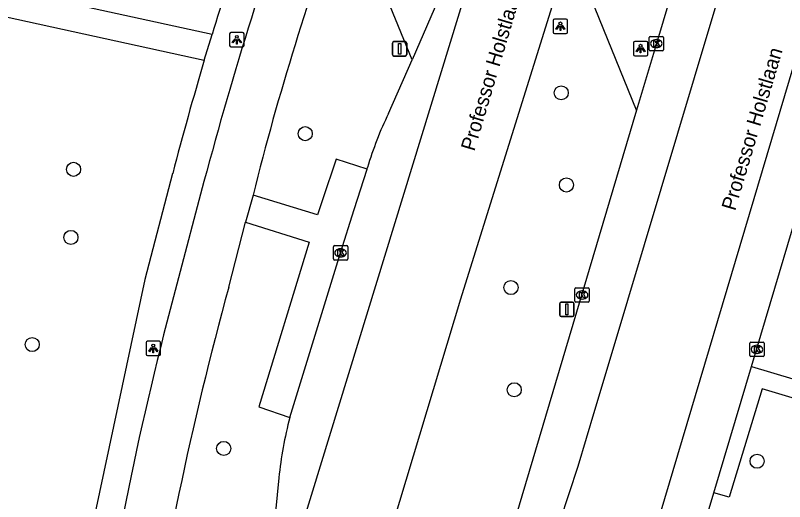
# Model space of a CAD drawing. Extents: x 159822 to 160765, y 380693 to 381634.
# Drawn here: x 160379.6 to 160432.9, y 380824 to 380857.8 of the extents above; entities that cross this region are included whole.
import ezdxf

# ---------------------------------------------------------------- set-up
doc = ezdxf.new("R2010")
doc.units = 0
for name, color, linetype in [('IMGEO_Berm_groen', 7, 'Continuous'), ('IMGEO_Boom', 7, 'Continuous'), ('IMGEO_Fietspad_gesloten', 7, 'Continuous'), ('IMGEO_Kolk', 7, 'Continuous'), ('IMGEO_Lichtpunt', 7, 'Continuous'), ('IMGEO_Openbare_ruimte_label', 7, 'Continuous'), ('IMGEO_Rijbaan_regionaal_gesloten', 7, 'Continuous'), ('IMGEO_Verkeersbordpaal', 7, 'Continuous'), ('IMGEO_Voetpad_halfverhard', 7, 'Continuous'), ('IMGEO_Voetpad_open', 7, 'Continuous')]:
    doc.layers.add(name, color=color, linetype=linetype)

msp = doc.modelspace()

# ---------------------------------------------------------------- linework, layer by layer
at = {"layer": 'IMGEO_Berm_groen'}
for points in [[(160407.126, 380854.699), (160402.508, 380865.998)], [(160422.694, 380851.192), (160418.106, 380862.477)]]:
    msp.add_lwpolyline(points, dxfattribs=at)
at = {"layer": 'IMGEO_Boom'}
for centre in [(160417.464, 380852.4), (160399.725, 380849.567), (160383.666, 380847.093), (160417.825, 380846.009), (160383.487, 380842.374), (160413.984, 380838.893), (160380.802, 380834.941), (160414.212, 380831.806), (160394.076, 380827.737), (160431.038, 380826.852)]:
    msp.add_circle(centre, 0.489, dxfattribs=at)
at = {"layer": 'IMGEO_Fietspad_gesloten'}
for points in [[(160392.709, 380846.25), (160390.838, 380839.14)], [(160396.107, 380845.302), (160395.593, 380843.438)], [(160394.421, 380838.922), (160395.593, 380843.438)]]:
    msp.add_lwpolyline(points, dxfattribs=at)
for centre, radius, start, end in [((160654.597, 380776.451), 271.03, 160.08749, 165.07638), ((160585.377, 380798.101), 195.067, 159.63071, 165.997), ((160619.543, 380777.36), 236.902, 164.8836, 171.94842), ((160622.56, 380776.424), 236.545, 164.67983, 171.81298)]:
    msp.add_arc(centre, radius, start, end, dxfattribs=at)
at = {"layer": 'IMGEO_Kolk'}
for p, q in [((160423.557, 380855.39), (160423.557, 380856.242)), ((160423.632, 380856.316), (160424.484, 380856.316)), ((160424.045, 380856.096), (160424.07, 380856.096)), ((160424.558, 380856.242), (160424.558, 380855.39)), ((160424.068, 380855.536), (160424.043, 380855.536)), ((160424.484, 380855.316), (160423.632, 380855.316)), ((160401.674, 380840.876), (160401.674, 380841.728)), ((160401.749, 380841.802), (160402.601, 380841.802)), ((160402.162, 380841.582), (160402.187, 380841.582)), ((160402.675, 380841.728), (160402.675, 380840.876)), ((160402.185, 380841.022), (160402.16, 380841.022)), ((160402.601, 380840.802), (160401.749, 380840.802)), ((160418.41, 380837.952), (160418.41, 380838.804)), ((160418.485, 380838.878), (160419.337, 380838.878)), ((160418.898, 380838.658), (160418.923, 380838.658)), ((160419.411, 380838.804), (160419.411, 380837.952)), ((160419.337, 380837.878), (160418.485, 380837.878)), ((160418.921, 380838.098), (160418.896, 380838.098)), ((160430.532, 380834.182), (160430.532, 380835.034)), ((160430.607, 380835.108), (160431.459, 380835.108)), ((160431.02, 380834.888), (160431.045, 380834.888)), ((160431.533, 380835.034), (160431.533, 380834.182)), ((160431.459, 380834.108), (160430.607, 380834.108)), ((160431.043, 380834.328), (160431.018, 380834.328))]:
    msp.add_line(p, q, dxfattribs=at)
for points in [[(160423.557, 380855.39), (160423.557, 380856.242)], [(160423.632, 380856.316), (160424.484, 380856.316)], [(160423.878, 380856.016), (160424.001, 380856.016), (160424.001, 380855.865), (160424.131, 380856.016), (160424.295, 380856.016), (160424.149, 380855.865), (160424.302, 380855.616), (160424.15, 380855.616), (160424.065, 380855.78), (160424.001, 380855.713), (160424.001, 380855.616), (160423.878, 380855.616), (160423.878, 380856.016)], [(160424.558, 380856.242), (160424.558, 380855.39)], [(160424.484, 380855.316), (160423.632, 380855.316)], [(160401.674, 380840.876), (160401.674, 380841.728)], [(160401.749, 380841.802), (160402.601, 380841.802)], [(160402.675, 380841.728), (160402.675, 380840.876)], [(160401.995, 380841.502), (160402.118, 380841.502), (160402.118, 380841.351), (160402.248, 380841.502), (160402.412, 380841.502), (160402.266, 380841.351), (160402.419, 380841.102), (160402.267, 380841.102), (160402.182, 380841.266), (160402.118, 380841.199), (160402.118, 380841.102), (160401.995, 380841.102), (160401.995, 380841.502)], [(160402.601, 380840.802), (160401.749, 380840.802)], [(160418.41, 380837.952), (160418.41, 380838.804)], [(160418.485, 380838.878), (160419.337, 380838.878)], [(160418.731, 380838.578), (160418.854, 380838.578), (160418.854, 380838.427), (160418.984, 380838.578), (160419.148, 380838.578), (160419.002, 380838.427), (160419.155, 380838.178), (160419.003, 380838.178), (160418.918, 380838.342), (160418.854, 380838.275), (160418.854, 380838.178), (160418.731, 380838.178), (160418.731, 380838.578)], [(160419.411, 380838.804), (160419.411, 380837.952)], [(160419.337, 380837.878), (160418.485, 380837.878)], [(160430.532, 380834.182), (160430.532, 380835.034)], [(160430.607, 380835.108), (160431.459, 380835.108)], [(160430.853, 380834.808), (160430.976, 380834.808), (160430.976, 380834.657), (160431.106, 380834.808), (160431.27, 380834.808), (160431.124, 380834.657), (160431.277, 380834.408), (160431.125, 380834.408), (160431.04, 380834.572), (160430.976, 380834.505), (160430.976, 380834.408), (160430.853, 380834.408), (160430.853, 380834.808)], [(160431.533, 380835.034), (160431.533, 380834.182)], [(160431.459, 380834.108), (160430.607, 380834.108)]]:
    msp.add_lwpolyline(points, dxfattribs=at)
for centre, start, end in [((160423.634, 380856.24), 91.552, 178.448), ((160423.634, 380856.24), 91.552, 178.448), ((160424.482, 380856.24), 1.552, 88.448), ((160424.482, 380856.24), 1.552, 88.448), ((160423.634, 380855.392), 181.552, 268.448), ((160423.634, 380855.392), 181.552, 268.448), ((160424.482, 380855.392), 271.552, 358.448), ((160424.482, 380855.392), 271.552, 358.448), ((160401.751, 380841.726), 91.552, 178.448), ((160401.751, 380841.726), 91.552, 178.448), ((160402.599, 380841.726), 1.552, 88.448), ((160402.599, 380841.726), 1.552, 88.448), ((160401.751, 380840.878), 181.552, 268.448), ((160401.751, 380840.878), 181.552, 268.448), ((160402.599, 380840.878), 271.552, 358.448), ((160402.599, 380840.878), 271.552, 358.448), ((160418.487, 380838.802), 91.552, 178.448), ((160418.487, 380838.802), 91.552, 178.448), ((160419.335, 380838.802), 1.552, 88.448), ((160419.335, 380838.802), 1.552, 88.448), ((160418.487, 380837.954), 181.552, 268.448), ((160418.487, 380837.954), 181.552, 268.448), ((160419.335, 380837.954), 271.552, 358.448), ((160419.335, 380837.954), 271.552, 358.448), ((160430.609, 380835.032), 91.552, 178.448), ((160430.609, 380835.032), 91.552, 178.448), ((160431.457, 380835.032), 1.552, 88.448), ((160431.457, 380835.032), 1.552, 88.448), ((160430.609, 380834.184), 181.552, 268.448), ((160430.609, 380834.184), 181.552, 268.448), ((160431.457, 380834.184), 271.552, 358.448), ((160431.457, 380834.184), 271.552, 358.448)]:
    msp.add_arc(centre, 0.0765, start, end, dxfattribs=at)
for centre, major_axis, ratio, start_param, end_param in [((160424.044, 380855.816), (-0.387, 0.002), 0.722429, 4.712389, 7.853982), ((160424.069, 380855.816), (-0.39, 0.002), 0.717154, 1.570796, 4.712389), ((160402.161, 380841.302), (-0.387, 0.002), 0.722429, 4.712389, 7.853982), ((160402.186, 380841.302), (-0.39, 0.002), 0.717154, 1.570796, 4.712389), ((160418.897, 380838.378), (-0.387, 0.002), 0.722429, 4.712389, 7.853982), ((160418.922, 380838.378), (-0.39, 0.002), 0.717154, 1.570796, 4.712389), ((160431.019, 380834.608), (-0.387, 0.002), 0.722429, 4.712389, 7.853982), ((160431.044, 380834.608), (-0.39, 0.002), 0.717154, 1.570796, 4.712389)]:
    msp.add_ellipse(centre, major_axis=major_axis, ratio=ratio, start_param=start_param, end_param=end_param, dxfattribs=at)
at = {"layer": 'IMGEO_Lichtpunt'}
for p, q in [((160416.909, 380857.419), (160416.909, 380856.612)), ((160416.909, 380857.419), (160416.909, 380856.612)), ((160417.811, 380857.514), (160417.003, 380857.514)), ((160417.811, 380857.514), (160417.003, 380857.514)), ((160417.905, 380856.612), (160417.905, 380857.419)), ((160417.905, 380856.612), (160417.905, 380857.419)), ((160394.486, 380856.486), (160394.486, 380855.679)), ((160394.486, 380856.486), (160394.486, 380855.679)), ((160395.388, 380856.581), (160394.58, 380856.581)), ((160395.388, 380856.581), (160394.58, 380856.581)), ((160395.482, 380855.679), (160395.482, 380856.486)), ((160395.482, 380855.679), (160395.482, 380856.486)), ((160417.003, 380856.518), (160417.811, 380856.518)), ((160417.003, 380856.518), (160417.811, 380856.518)), ((160423.372, 380855.967), (160422.564, 380855.967)), ((160423.372, 380855.967), (160422.564, 380855.967)), ((160394.58, 380855.585), (160395.388, 380855.585)), ((160394.58, 380855.585), (160395.388, 380855.585)), ((160422.47, 380855.872), (160422.47, 380855.065)), ((160422.47, 380855.872), (160422.47, 380855.065)), ((160423.466, 380855.065), (160423.466, 380855.872)), ((160423.466, 380855.065), (160423.466, 380855.872)), ((160422.564, 380854.971), (160423.372, 380854.971)), ((160422.564, 380854.971), (160423.372, 380854.971)), ((160389.6, 380835.167), (160388.792, 380835.167)), ((160389.6, 380835.167), (160388.792, 380835.167)), ((160388.698, 380835.072), (160388.698, 380834.265)), ((160388.698, 380835.072), (160388.698, 380834.265)), ((160389.694, 380834.265), (160389.694, 380835.072)), ((160389.694, 380834.265), (160389.694, 380835.072)), ((160388.792, 380834.171), (160389.6, 380834.171)), ((160388.792, 380834.171), (160389.6, 380834.171))]:
    msp.add_line(p, q, dxfattribs=at)
for points in [[(160417.283, 380857.083), (160417.322, 380857.055), (160417.134, 380856.793), (160417.096, 380856.82), (160417.283, 380857.083)], [(160417.385, 380857.035), (160417.432, 380857.035), (160417.432, 380856.713), (160417.385, 380856.713), (160417.385, 380857.035)], [(160417.495, 380857.055), (160417.533, 380857.082), (160417.72, 380856.82), (160417.681, 380856.792), (160417.495, 380857.055)], [(160394.86, 380856.15), (160394.899, 380856.122), (160394.711, 380855.86), (160394.673, 380855.887), (160394.86, 380856.15)], [(160394.962, 380856.102), (160395.009, 380856.102), (160395.009, 380855.78), (160394.962, 380855.78), (160394.962, 380856.102)], [(160395.072, 380856.122), (160395.11, 380856.149), (160395.297, 380855.887), (160395.258, 380855.859), (160395.072, 380856.122)], [(160422.844, 380855.536), (160422.883, 380855.508), (160422.695, 380855.246), (160422.657, 380855.273), (160422.844, 380855.536)], [(160422.946, 380855.488), (160422.993, 380855.488), (160422.993, 380855.166), (160422.946, 380855.166), (160422.946, 380855.488)], [(160423.056, 380855.508), (160423.094, 380855.535), (160423.281, 380855.273), (160423.242, 380855.245), (160423.056, 380855.508)], [(160389.072, 380834.736), (160389.111, 380834.708), (160388.923, 380834.446), (160388.885, 380834.473), (160389.072, 380834.736)], [(160389.174, 380834.688), (160389.221, 380834.688), (160389.221, 380834.366), (160389.174, 380834.366), (160389.174, 380834.688)], [(160389.284, 380834.708), (160389.322, 380834.735), (160389.509, 380834.473), (160389.47, 380834.445), (160389.284, 380834.708)]]:
    msp.add_lwpolyline(points, dxfattribs=at)
for centre in [(160417.408, 380857.217), (160394.985, 380856.284), (160422.969, 380855.67), (160389.197, 380834.87)]:
    msp.add_circle(centre, 0.0994, dxfattribs=at)
for centre, start, end in [((160417.003, 380857.419), 90, 180), ((160417.003, 380857.419), 90, 180), ((160417.811, 380857.419), 0, 90), ((160417.811, 380857.419), 0, 90), ((160394.58, 380856.486), 90, 180), ((160394.58, 380856.486), 90, 180), ((160395.388, 380856.486), 0, 90), ((160395.388, 380856.486), 0, 90), ((160417.003, 380856.612), 180, 270), ((160417.003, 380856.612), 180, 270), ((160417.811, 380856.612), 270, 0), ((160417.811, 380856.612), 270, 360), ((160422.564, 380855.872), 90, 180), ((160422.564, 380855.872), 90, 180), ((160423.372, 380855.872), 0, 90), ((160423.372, 380855.872), 0, 90), ((160394.58, 380855.679), 180, 270), ((160394.58, 380855.679), 180, 270), ((160395.388, 380855.679), 270, 0), ((160395.388, 380855.679), 270, 360), ((160422.564, 380855.065), 180, 270), ((160422.564, 380855.065), 180, 270), ((160423.372, 380855.065), 270, 0), ((160423.372, 380855.065), 270, 360), ((160388.792, 380835.072), 90, 180), ((160388.792, 380835.072), 90, 180), ((160389.6, 380835.072), 0, 90), ((160389.6, 380835.072), 0, 90), ((160388.792, 380834.265), 180, 270), ((160388.792, 380834.265), 180, 270), ((160389.6, 380834.265), 270, 0), ((160389.6, 380834.265), 270, 360)]:
    msp.add_arc(centre, 0.0946, start, end, dxfattribs=at)
at = {"layer": 'IMGEO_Rijbaan_regionaal_gesloten'}
for points in [[(160429.762, 380874.897), (160424.059, 380855.816), (160422.694, 380851.192)], [(160432.899, 380874.266), (160432.513, 380872.928), (160430.008, 380864.588), (160428.979, 380861.16), (160427.826, 380857.301), (160426.673, 380853.441), (160425.519, 380849.582), (160424.366, 380845.722), (160423.213, 380841.863), (160422.06, 380838.004), (160420.907, 380834.144), (160419.781, 380830.378), (160418.615, 380826.473), (160417.371, 380822.695), (160415.807, 380819.038), (160414.093, 380815.358), (160412.198, 380811.87), (160410.083, 380808.446), (160408.095, 380805.162), (160404.706, 380799.408)], [(160439.125, 380873.012), (160424.303, 380823.144), (160419.641, 380808.928)], [(160396.424, 380812.288), (160414.779, 380872.202)], [(160413.745, 380869.736), (160409.197, 380859.452), (160407.126, 380854.699)], [(160398.267, 380797.475), (160410.502, 380838.119), (160418.106, 380862.477)], [(160405.499, 380850.966), (160407.126, 380854.699)], [(160422.694, 380851.192), (160413.604, 380820.621), (160410.085, 380811.841), (160406.037, 380802.469)], [(160430.648, 380833.412), (160435.11, 380848.397)], [(160398.661, 380829.884), (160402.176, 380841.302), (160403.118, 380844.298), (160404.008, 380847.112)], [(160404.008, 380847.112), (160404.043, 380847.223)], [(160428.044, 380824.666), (160430.648, 380833.412)], [(160397.902, 380825.704), (160396.887, 380815.32), (160396.424, 380812.288)], [(160425.736, 380816.917), (160428.044, 380824.666)]]:
    msp.add_lwpolyline(points, dxfattribs=at)
for centre, radius, start, end in [((160426.587, 380840.608), 23.494, 153.8411, 163.6476), ((160422.919, 380823.32), 25.131, 164.8597, 174.5572)]:
    msp.add_arc(centre, radius, start, end, dxfattribs=at)
at = {"layer": 'IMGEO_Verkeersbordpaal'}
for p, q in [((160405.87, 380855.95), (160406.66, 380855.95)), ((160406.66, 380855.95), (160405.87, 380855.95)), ((160405.77, 380855.05), (160405.77, 380855.85)), ((160405.77, 380855.85), (160405.77, 380855.05)), ((160406.76, 380855.85), (160406.76, 380855.05)), ((160406.76, 380855.05), (160406.76, 380855.85)), ((160406.66, 380854.95), (160405.87, 380854.95)), ((160405.87, 380854.95), (160406.66, 380854.95)), ((160417.46, 380837.882), (160418.25, 380837.882)), ((160418.25, 380837.882), (160417.46, 380837.882)), ((160417.36, 380836.982), (160417.36, 380837.782)), ((160417.36, 380837.782), (160417.36, 380836.982)), ((160418.35, 380837.782), (160418.35, 380836.982)), ((160418.35, 380836.982), (160418.35, 380837.782)), ((160418.25, 380836.882), (160417.46, 380836.882)), ((160417.46, 380836.882), (160418.25, 380836.882))]:
    msp.add_line(p, q, dxfattribs=at)
for points in [[(160406.19, 380855.825), (160406.34, 380855.825), (160406.34, 380855.075), (160406.19, 380855.075), (160406.19, 380855.825)], [(160417.78, 380837.757), (160417.93, 380837.757), (160417.93, 380837.007), (160417.78, 380837.007), (160417.78, 380837.757)]]:
    msp.add_lwpolyline(points, dxfattribs=at)
for centre, start, end in [((160405.87, 380855.85), 90, 180), ((160405.87, 380855.85), 90, 180), ((160406.66, 380855.85), 0, 90), ((160406.66, 380855.85), 360, 90), ((160405.87, 380855.05), 180, 270), ((160405.87, 380855.05), 180, 270), ((160406.66, 380855.05), 270, 0), ((160406.66, 380855.05), 270, 0), ((160417.46, 380837.782), 90, 180), ((160417.46, 380837.782), 90, 180), ((160418.25, 380837.782), 0, 90), ((160418.25, 380837.782), 360, 90), ((160417.46, 380836.982), 180, 270), ((160417.46, 380836.982), 180, 270), ((160418.25, 380836.982), 270, 0), ((160418.25, 380836.982), 270, 0)]:
    msp.add_arc(centre, 0.1, start, end, dxfattribs=at)
at = {"layer": 'IMGEO_Voetpad_halfverhard'}
for points in [[(160393.271, 380856.456), (160371.381, 380861.23), (160368.909, 380861.646), (160366.707, 380861.94), (160365.797, 380861.977)], [(160365.512, 380860.318), (160366.988, 380860.245), (160368.799, 380859.927), (160370.646, 380859.523), (160392.731, 380854.669)]]:
    msp.add_lwpolyline(points, dxfattribs=at)
at = {"layer": 'IMGEO_Voetpad_open'}
for points in [[(160392.731, 380854.669), (160393.271, 380856.456)], [(160404.008, 380847.112), (160401.869, 380847.789), (160400.926, 380844.982), (160400.575, 380843.937), (160396.107, 380845.302)], [(160390.538, 380846.809), (160388.617, 380839.457), (160383.291, 380814.509), (160381.213, 380800.348), (160380.068, 380793.081)], [(160395.593, 380843.438), (160400.006, 380842.04), (160396.501, 380830.611), (160398.661, 380829.884)], [(160430.648, 380833.412), (160436.385, 380831.707)], [(160436.023, 380830.479), (160431.384, 380831.869), (160429.114, 380824.347), (160428.044, 380824.666)]]:
    msp.add_lwpolyline(points, dxfattribs=at)
for centre, radius, start, end in [((160616.995, 380787.808), 234.019, 159.56554, 162.94166), ((160618.034, 380787.572), 235.081, 163.41601, 165.40497)]:
    msp.add_arc(centre, radius, start, end, dxfattribs=at)

# ---------------------------------------------------------------- texts
at = {"layer": 'IMGEO_Openbare_ruimte_label'}
for p in [(160411.445, 380848.304), (160429.511, 380844.173)]:
    msp.add_text('Professor Holstlaan', height=1, rotation=73.5038, dxfattribs=at).set_placement(p)

doc.saveas('drawing.dxf')
